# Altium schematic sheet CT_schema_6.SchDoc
size 287 x 160 mm
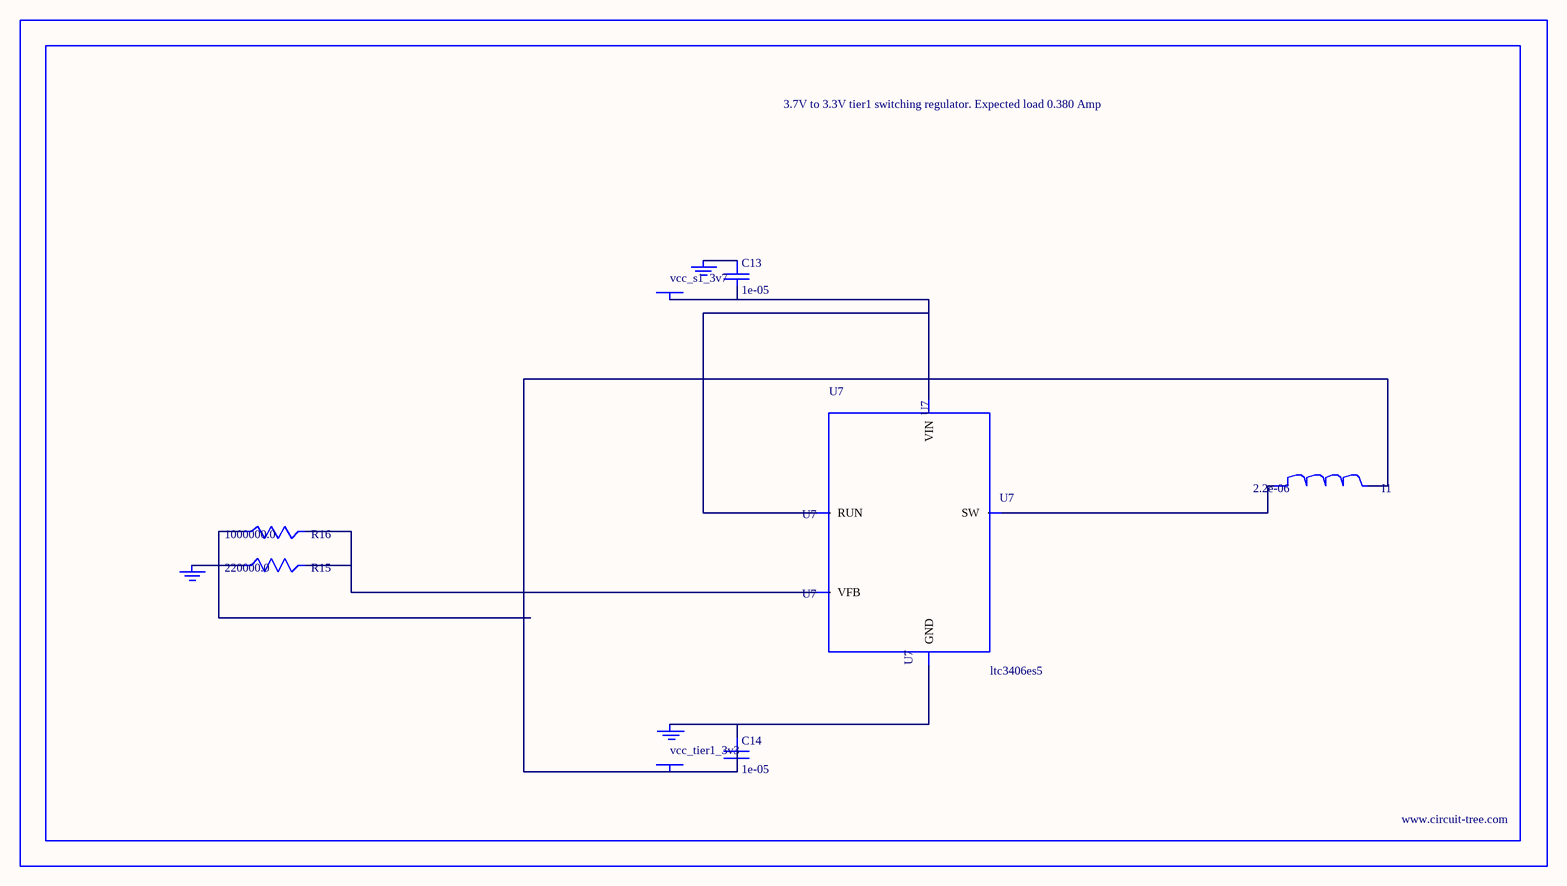
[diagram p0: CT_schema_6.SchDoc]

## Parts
BORDER5  (no value)
C13  1e-05  [C0805]
C14  1e-05  [C0805]
GND_INSTANCE_5_0  (no value)
GND_INSTANCE_5_1  (no value)
GND_INSTANCE_5_2  (no value)
I1  2.2e-06  [L0805]
POWER_INSTANCE_5_0  vcc_tier1_3v3
POWER_INSTANCE_5_1  vcc_s1_3v7
R15  220000.0  [R0603]
R16  1000000.0  [R0603]
U7  ltc3406es5  [TSOT-23-5]

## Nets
NetC13_1: C13.1 GND_INSTANCE_5_1.0(GND)
NetC13_2: C13.2 POWER_INSTANCE_5_1.0(PWR) U7.1(RUN) U7.4(VIN)
NetC14_1: C14.1 GND_INSTANCE_5_0.0(GND) U7.2(GND)
NetC14_2: C14.2 I1.2 POWER_INSTANCE_5_0.0(PWR) R16.1
NetGND_INSTANCE_5_2_0: GND_INSTANCE_5_2.0(GND) R15.1
NetI1_1: I1.1 U7.3(SW)
NetR15_2: R15.2 R16.2 U7.5(VFB)

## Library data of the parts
BORDER5 = BORDER_PAGE5
C13 C14 = C0805C106K8RACTU
GND_INSTANCE_5_0-GND_INSTANCE_5_2 = GND
I1 = L0805C2R2MDWIT
POWER_INSTANCE_5_0 POWER_INSTANCE_5_1 = PWR
R15 = RC0603JR-07220KL
R16 = RC0603JR-071ML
